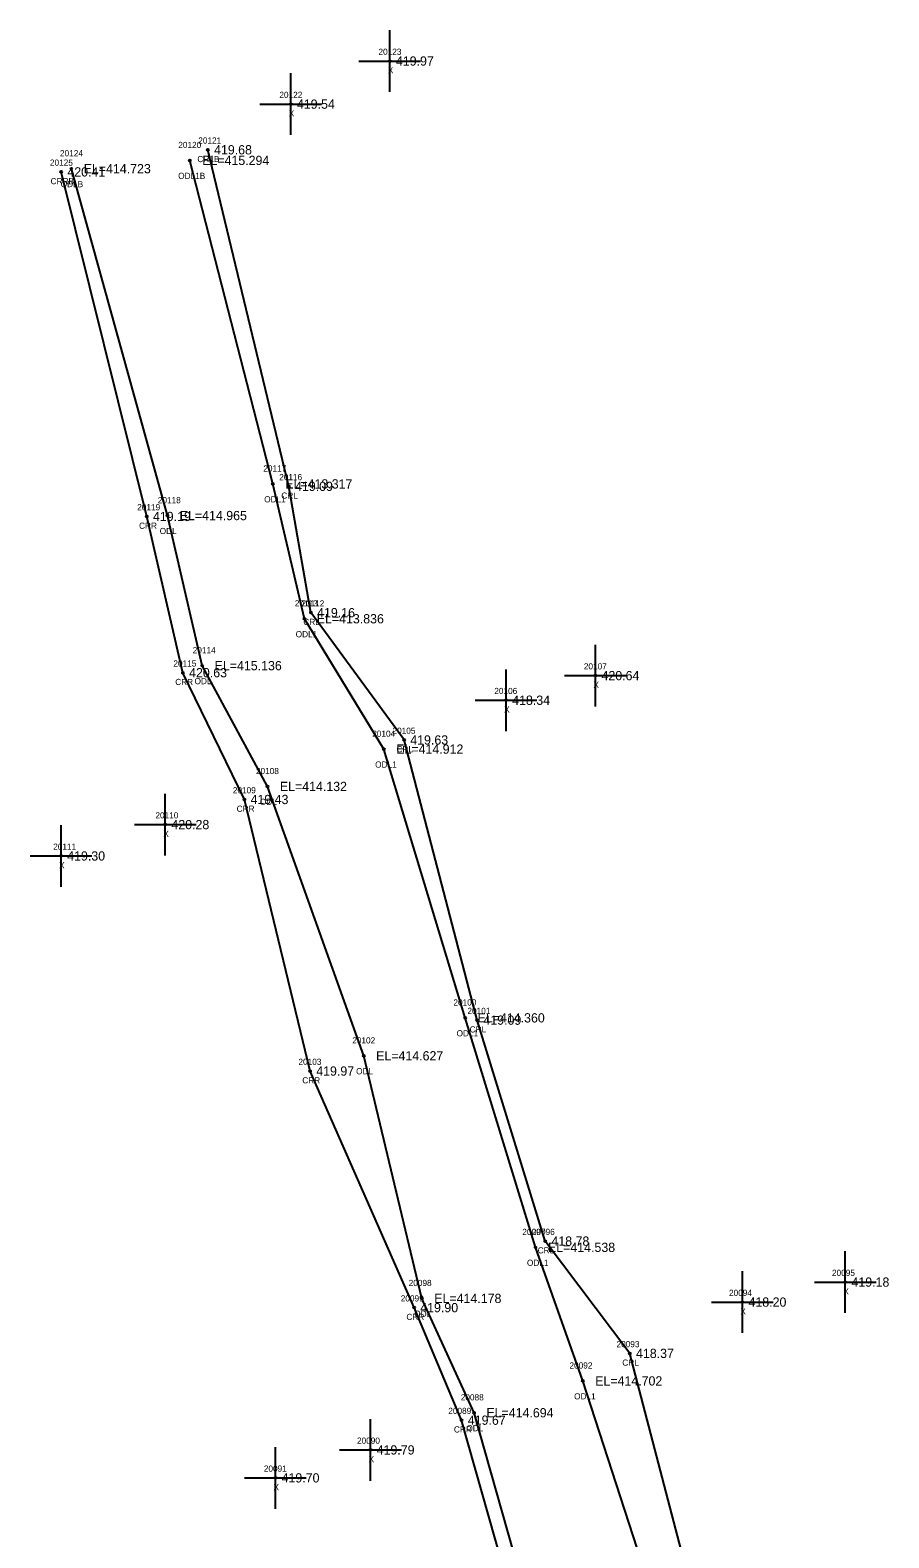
# Model space of a CAD drawing. Extents: x 1613184 to 1614731, y 770859 to 771868.
# Drawn here: x 1613807.2 to 1613946.3, y 771623.6 to 771867.9 of the extents above; entities that cross this region are included whole.
import ezdxf

# ---------------------------------------------------------------- set-up
doc = ezdxf.new("R2010")
doc.units = 0
for name, color, linetype in [('RD_EX_H2O', 7, 'Continuous'), ('RD_EX_H2O_txCode', 7, 'Continuous'), ('RD_EX_Misc', 7, 'Continuous'), ('RD_EX_Misc_txCode', 7, 'Continuous'), ('RD_EX_TX_H2O_ELEV', 7, 'Continuous'), ('RD_EX_TX_Misc_ELEV', 7, 'Continuous'), ('RD_SMD_Locator', 7, 'Continuous')]:
    doc.layers.add(name, color=color, linetype=linetype)

msp = doc.modelspace()

# ---------------------------------------------------------------- linework, layer by layer
at = {"layer": 'RD_EX_H2O'}
for points in [[(1613935.44, 771356.77), (1613943.27, 771455.38), (1613930.01, 771555.13), (1613904.31, 771653.52), (1613890.61, 771671.71), (1613879.59, 771707.51), (1613867.74, 771752.9), (1613852.65, 771773.53), (1613849.08, 771793.99), (1613835.96, 771848.52)], [(1613933.56, 771356.85), (1613941.09, 771457.11), (1613927.24, 771554.95), (1613896.69, 771649.06), (1613889.05, 771670.7), (1613877.65, 771707.88), (1613864.46, 771751.42), (1613851.59, 771772.54), (1613846.49, 771794.39), (1613833.03, 771846.8)], [(1613917.33, 771358.45), (1613914.84, 771377.38), (1613920.97, 771458.1), (1613902.34, 771553.43), (1613877.06, 771642.7), (1613869.36, 771660.93), (1613852.51, 771699.26), (1613841.87, 771743.26), (1613831.92, 771763.8), (1613826.06, 771789.11), (1613812.2, 771844.94)], [(1613918.86, 771358.4), (1613923.07, 771457.63), (1613904.68, 771553.56), (1613879.07, 771643.9), (1613870.63, 771662.43), (1613861.21, 771701.73), (1613845.61, 771745.37), (1613835.05, 771764.94), (1613829.4, 771789.26), (1613813.84, 771845.46)]]:
    msp.add_lwpolyline(points, dxfattribs=at)
at = {"layer": 'RD_EX_Misc'}
for p, q in [((1613865.42, 771857.9), (1613865.42, 771867.9)), ((1613849.38, 771850.92), (1613849.38, 771860.92)), ((1613860.42, 771862.9), (1613870.42, 771862.9)), ((1613844.38, 771855.92), (1613854.38, 771855.92)), ((1613898.72, 771758.33), (1613898.72, 771768.33)), ((1613884.25, 771754.34), (1613884.25, 771764.34)), ((1613893.72, 771763.33), (1613903.72, 771763.33)), ((1613879.25, 771759.34), (1613889.25, 771759.34)), ((1613829.05, 771734.19), (1613829.05, 771744.19)), ((1613812.17, 771729.11), (1613812.17, 771739.11)), ((1613824.05, 771739.19), (1613834.05, 771739.19)), ((1613807.17, 771734.11), (1613817.17, 771734.11)), ((1613939.21, 771660.07), (1613939.21, 771670.07)), ((1613922.53, 771656.83), (1613922.53, 771666.83)), ((1613934.21, 771665.07), (1613944.21, 771665.07)), ((1613917.53, 771661.83), (1613927.53, 771661.83)), ((1613862.3, 771632.88), (1613862.3, 771642.88)), ((1613846.9, 771628.35), (1613846.9, 771638.35)), ((1613857.3, 771637.88), (1613867.3, 771637.88)), ((1613841.9, 771633.35), (1613851.9, 771633.35))]:
    msp.add_line(p, q, dxfattribs=at)
at = {"layer": 'RD_SMD_Locator'}
for centre in [(1613865.42, 771862.9), (1613849.38, 771855.92), (1613835.96, 771848.52), (1613833.03, 771846.8), (1613812.2, 771844.94), (1613813.84, 771845.46), (1613846.49, 771794.39), (1613849.08, 771793.99), (1613826.06, 771789.11), (1613829.4, 771789.26), (1613852.65, 771773.53), (1613851.59, 771772.54), (1613831.92, 771763.8), (1613835.05, 771764.94), (1613898.72, 771763.33), (1613884.25, 771759.34), (1613864.46, 771751.42), (1613867.74, 771752.9), (1613845.61, 771745.37), (1613841.87, 771743.26), (1613829.05, 771739.19), (1613812.17, 771734.11), (1613877.65, 771707.88), (1613879.59, 771707.51), (1613861.21, 771701.73), (1613852.51, 771699.26), (1613889.05, 771670.7), (1613890.61, 771671.71), (1613939.21, 771665.07), (1613869.36, 771660.93), (1613870.63, 771662.43), (1613922.53, 771661.83), (1613904.31, 771653.52), (1613896.69, 771649.06), (1613879.07, 771643.9), (1613877.06, 771642.7), (1613862.3, 771637.88), (1613846.9, 771633.35)]:
    msp.add_circle(centre, 0.15, dxfattribs=at)

# ---------------------------------------------------------------- texts
at = {"layer": 'RD_EX_H2O_txCode'}
for s, p in [('20120', (1613831.16, 771848.8)), ('20121', (1613834.4, 771849.52)), ('20125', (1613810.37, 771845.94)), ('20124', (1613812, 771847.46)), ('CRLB', (1613834.25, 771846.52)), ('CRRB', (1613810.48, 771842.94)), ('ODL1B', (1613831.15, 771843.8)), ('ODLB', (1613812.12, 771842.46)), ('20117', (1613844.94, 771796.39)), ('20116', (1613847.51, 771794.99)), ('ODL1', (1613845.08, 771791.39)), ('CRL', (1613847.85, 771791.99)), ('20119', (1613824.51, 771790.11)), ('20118', (1613827.85, 771791.26)), ('CRR', (1613824.81, 771787.11)), ('ODL', (1613828.15, 771786.26)), ('20113', (1613850.04, 771774.54)), ('20112', (1613851.1, 771774.53)), ('ODL1', (1613850.18, 771769.54)), ('CRL', (1613851.42, 771771.53)), ('20114', (1613833.5, 771766.94)), ('20115', (1613830.37, 771764.8)), ('CRR', (1613830.67, 771761.8)), ('ODL', (1613833.8, 771761.94)), ('20104', (1613862.58, 771753.42)), ('20105', (1613865.86, 771753.9)), ('CRL', (1613866.51, 771750.9)), ('20108', (1613843.74, 771747.37)), ('ODL1', (1613863.05, 771748.42)), ('20109', (1613840, 771744.26)), ('CRR', (1613840.62, 771741.26)), ('ODL', (1613844.37, 771742.37)), ('20100', (1613875.73, 771709.88)), ('20101', (1613878, 771708.51)), ('20102', (1613859.34, 771703.73)), ('ODL1', (1613876.24, 771704.88)), ('CRL', (1613878.36, 771705.51)), ('20103', (1613850.63, 771700.26)), ('ODL', (1613859.97, 771698.73)), ('CRR', (1613851.25, 771697.26)), ('20097', (1613886.89, 771672.7)), ('20096', (1613888.43, 771672.71)), ('CRL', (1613889.38, 771669.71)), ('ODL1', (1613887.64, 771667.7)), ('20098', (1613868.48, 771664.43)), ('20099', (1613867.2, 771661.93)), ('ODL', (1613869.39, 771659.43)), ('CRR', (1613868.11, 771658.93)), ('20093', (1613902.15, 771654.52)), ('20092', (1613894.53, 771651.06)), ('CRL', (1613903.08, 771651.52)), ('20088', (1613876.92, 771645.9)), ('ODL1', (1613895.28, 771646.06)), ('20089', (1613874.9, 771643.7)), ('CRR', (1613875.81, 771640.7)), ('ODL', (1613877.83, 771640.9))]:
    msp.add_text(s, height=1, dxfattribs=at).set_placement(p)
at = {"layer": 'RD_EX_Misc_txCode'}
for s, p in [('20123', (1613863.59, 771863.9)), ('X', (1613865.11, 771860.9)), ('20122', (1613847.54, 771856.92)), ('X', (1613849.06, 771853.92)), ('20107', (1613896.85, 771764.33)), ('20106', (1613882.35, 771760.34)), ('X', (1613898.41, 771761.33)), ('X', (1613883.94, 771757.34)), ('20110', (1613827.46, 771740.19)), ('20111', (1613810.9, 771735.11)), ('X', (1613828.73, 771737.19)), ('X', (1613811.85, 771732.11)), ('20095', (1613937.05, 771666.07)), ('20094', (1613920.37, 771662.83)), ('X', (1613938.9, 771663.07)), ('X', (1613922.21, 771659.83)), ('20090', (1613860.11, 771638.88)), ('X', (1613861.99, 771635.88)), ('20091', (1613845.02, 771634.35)), ('X', (1613846.58, 771631.35))]:
    msp.add_text(s, height=1, dxfattribs=at).set_placement(p)
at = {"layer": 'RD_EX_TX_H2O_ELEV'}
for s, p in [('419.68', (1613836.96, 771847.77)), ('EL=414.723', (1613815.84, 771844.71)), ('EL=415.294', (1613835.03, 771846.05)), ('420.41', (1613813.2, 771844.19)), ('EL=413.317', (1613848.49, 771793.64)), ('419.09', (1613850.08, 771793.24)), ('419.19', (1613827.06, 771788.36)), ('EL=414.965', (1613831.4, 771788.51)), ('419.16', (1613853.65, 771772.78)), ('EL=413.836', (1613853.59, 771771.79)), ('EL=415.136', (1613837.05, 771764.19)), ('420.63', (1613832.92, 771763.05)), ('419.63', (1613868.74, 771752.15)), ('EL=414.912', (1613866.46, 771750.67)), ('EL=414.132', (1613847.61, 771744.62)), ('419.43', (1613842.87, 771742.51)), ('EL=414.360', (1613879.65, 771707.13)), ('419.09', (1613880.59, 771706.76)), ('EL=414.627', (1613863.21, 771700.98)), ('419.97', (1613853.51, 771698.51)), ('EL=414.538', (1613891.05, 771669.95)), ('418.78', (1613891.61, 771670.96)), ('EL=414.178', (1613872.63, 771661.68)), ('419.90', (1613870.36, 771660.18)), ('418.37', (1613905.31, 771652.77)), ('EL=414.702', (1613898.69, 771648.31)), ('419.67', (1613878.06, 771641.95)), ('EL=414.694', (1613881.07, 771643.15))]:
    msp.add_text(s, height=1.5, dxfattribs=at).set_placement(p)
at = {"layer": 'RD_EX_TX_Misc_ELEV'}
for s, p in [('419.97', (1613866.42, 771862.15)), ('419.54', (1613850.38, 771855.17)), ('420.64', (1613899.72, 771762.58)), ('418.34', (1613885.25, 771758.59)), ('420.28', (1613830.05, 771738.44)), ('419.30', (1613813.17, 771733.36)), ('419.18', (1613940.21, 771664.32)), ('418.20', (1613923.53, 771661.08)), ('419.79', (1613863.3, 771637.13)), ('419.70', (1613847.9, 771632.6))]:
    msp.add_text(s, height=1.5, dxfattribs=at).set_placement(p)

doc.saveas('drawing.dxf')
